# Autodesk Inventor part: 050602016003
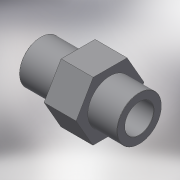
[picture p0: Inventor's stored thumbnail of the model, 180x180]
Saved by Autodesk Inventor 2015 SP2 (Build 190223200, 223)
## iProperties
Created: 2017-10
Part Number: 050602016003
Material: Generic
Description: PLASSON NIPPLE THR-CEM PVC 16(12)3/8"
Document SubType Name: Modeling
Designer: KIM
Mass: 6.47185 g
Surface Area: 41.6302 cm^2
Volume: 6.47185 cm^3
Density: 1 g/cm^3
Appearance: Default
Author: KIM
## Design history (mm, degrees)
derived "050602.ipt"
feature "Solid1::050602.ipt"
tag "TaggingFeature1"
body "Solid1"
other parameters: "d0" = 37, "d2" = 22, "d13" = 0, "d14" = 0.12, "d17" = 14, "d18" = 13.2, "d19" = 16, "d20" = 12, "d21" = 16.662, "d22" = 12, "d23" = 11.4, "d24" = 10.8, "d25" = 11, "d26" = -14, "d_" = 12, "R_" = 16.662, "C_" = 22, "B_" = 12, "L_" = 14, "lt_" = 11, "H_" = 37, "D_" = 16, "l_" = 12
